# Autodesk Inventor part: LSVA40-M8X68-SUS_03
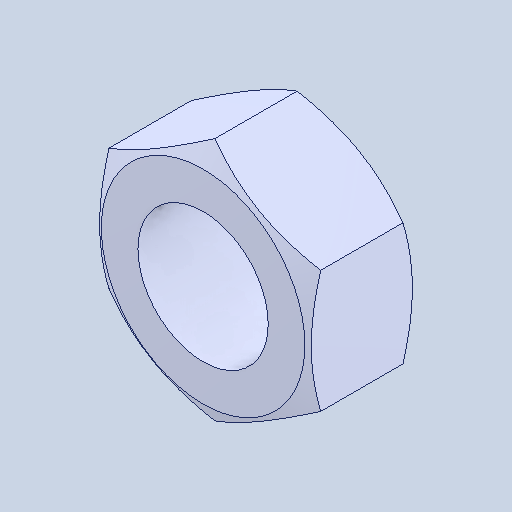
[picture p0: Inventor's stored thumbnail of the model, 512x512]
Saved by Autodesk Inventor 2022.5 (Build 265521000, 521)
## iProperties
Created: 2024-08
Part Number: LSVA40-M8X68-SUS_03
Material: 一般
Document SubType Name: Modeling
Designer: ImaoCorp
Density: 1 g/cm^3
Appearance: 既定
Author: ImaoCorp
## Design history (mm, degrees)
feature "LSVA40-M8X68-SUS_03"
node "ソリッド1"
